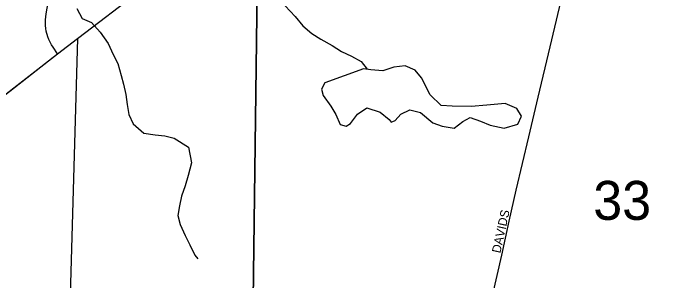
# Model space of a CAD drawing. Extents: x -9.1 to 34, y -3.1 to 22.
# Drawn here: x 3.961 to 4.682, y 18.292 to 18.579 of the extents above; entities that cross this region are included whole.
import ezdxf

# ---------------------------------------------------------------- set-up
doc = ezdxf.new("R2010")
doc.units = 0
for name, color, linetype in [('GM_X_City_Street', 7, 'Continuous'), ('GM_X_City_Street_Text', 7, 'Continuous'), ('GM_X_Corporation', 7, 'Continuous'), ('GM_X_Minor_Lake', 7, 'Continuous'), ('GM_X_Minor_River', 7, 'Continuous'), ('GM_X_Section', 7, 'Continuous'), ('GM_X_Section_Text', 7, 'Continuous'), ('GM_X_State_Route', 7, 'Continuous')]:
    doc.layers.add(name, color=color, linetype=linetype)

msp = doc.modelspace()

# ---------------------------------------------------------------- linework, layer by layer
at = {"layer": 'GM_X_City_Street'}
for points in [[(4.47636, 18.27506), (4.48661, 18.31901), (4.49442, 18.35546), (4.50193, 18.38876), (4.51566, 18.44616), (4.52552, 18.48852), (4.53842, 18.54291), (4.54863, 18.58519), (4.56037, 18.63668), (4.56565, 18.66061)], [(4.00828, 18.5352), (4.00347, 18.54237), (4.00172, 18.54495), (4.00023, 18.5477), (3.99896, 18.55055), (3.99785, 18.55347), (3.99612, 18.55946), (3.99557, 18.56253), (3.99529, 18.56563), (3.99535, 18.57188), (3.996, 18.57809), (3.9981, 18.5904), (3.99988, 18.60277), (4.00132, 18.61517), (4.00215, 18.62763), (4.00231, 18.63659)]]:
    msp.add_lwpolyline(points, dxfattribs=at)
at = {"layer": 'GM_X_Corporation'}
msp.add_lwpolyline([(3.93993, 18.48223), (4.00829, 18.5352), (4.02978, 18.55166), (4.02208, 18.27579), (4.21178, 18.27348), (4.21067, 18.18105), (4.45778, 18.17878), (4.47822, 18.26894), (4.48446, 18.26888), (4.48709, 18.28022), (4.70754, 18.2776)], dxfattribs=at)
at = {"layer": 'GM_X_Minor_Lake'}
for points in [[(4.29607, 18.50411), (4.29255, 18.49735), (4.29433, 18.49049), (4.30246, 18.47898), (4.30799, 18.47016), (4.31273, 18.45946), (4.31912, 18.45746), (4.3237, 18.46041), (4.33105, 18.47052), (4.34137, 18.47717), (4.35566, 18.47275), (4.36536, 18.46462), (4.36758, 18.46193), (4.37177, 18.46375), (4.37793, 18.47047), (4.38746, 18.47524), (4.39913, 18.47238), (4.41218, 18.46116), (4.42233, 18.45757), (4.43515, 18.45545), (4.44472, 18.46249), (4.45235, 18.46691), (4.46363, 18.46293), (4.47414, 18.45857), (4.48921, 18.45528), (4.50365, 18.45958), (4.50757, 18.46823), (4.50279, 18.47666), (4.49002, 18.48181), (4.47034, 18.48025), (4.45368, 18.47864), (4.43327, 18.479), (4.42118, 18.47958), (4.40927, 18.49116), (4.40012, 18.50952), (4.39345, 18.5176), (4.38256, 18.52234), (4.37044, 18.52103), (4.35866, 18.51706), (4.34544, 18.51805), (4.33752, 18.51932)], [(4.33752, 18.51932), (4.29607, 18.50411)]]:
    msp.add_lwpolyline(points, dxfattribs=at)
at = {"layer": 'GM_X_Minor_River'}
for points in [[(4.02896, 18.58417), (4.03483, 18.57308), (4.04497, 18.56911), (4.05425, 18.55871), (4.06275, 18.54643), (4.06822, 18.53459), (4.07336, 18.52502), (4.07693, 18.51207), (4.07942, 18.50254), (4.08188, 18.4915), (4.08322, 18.48086), (4.08494, 18.47022), (4.08968, 18.4599), (4.10124, 18.44984), (4.11331, 18.44812), (4.12388, 18.44718), (4.13404, 18.44472), (4.14938, 18.43498), (4.15251, 18.41824)], [(4.25319, 18.58675), (4.26397, 18.57557), (4.2725, 18.56519), (4.28219, 18.55706), (4.29192, 18.5512), (4.30391, 18.54417), (4.31401, 18.53793), (4.32489, 18.53281), (4.335, 18.52695), (4.34168, 18.51865)], [(4.15251, 18.41824), (4.14889, 18.40466), (4.14568, 18.39334), (4.14172, 18.38241), (4.13965, 18.37183), (4.13797, 18.36162), (4.14046, 18.35172), (4.14556, 18.33988), (4.15069, 18.32993), (4.15618, 18.31884), (4.15952, 18.31499)]]:
    msp.add_lwpolyline(points, dxfattribs=at)
at = {"layer": 'GM_X_Section'}
for points in [[(3.22195, 18.78578), (4.22542, 18.77097), (4.21254, 17.77165), (3.20939, 17.77812)], [(4.22542, 18.77097), (5.22068, 18.771), (5.21493, 17.76405), (4.21254, 17.77165)]]:
    msp.add_lwpolyline(points, close=True, dxfattribs=at)
at = {"layer": 'GM_X_State_Route'}
for points in [[(4.02978, 18.55166), (4.05374, 18.57001), (4.07365, 18.58504), (4.11277, 18.6153), (4.12971, 18.62841), (4.1384, 18.63523), (4.14685, 18.64188), (4.17126, 18.6613), (4.1932, 18.6788), (4.21521, 18.69641), (4.24213, 18.7175), (4.26162, 18.73304), (4.28825, 18.75436), (4.30525, 18.76806), (4.31477, 18.77541)], [(3.71152, 18.30501), (3.76488, 18.3463), (3.78489, 18.36179), (3.81394, 18.38426), (3.81908, 18.38824), (3.85835, 18.41895), (3.88546, 18.43991), (3.90179, 18.45264), (3.91986, 18.46674), (3.93993, 18.48223), (3.95686, 18.49529), (4.00361, 18.53162), (4.00828, 18.5352), (4.02978, 18.55166)]]:
    msp.add_lwpolyline(points, dxfattribs=at)

# ---------------------------------------------------------------- texts
at = {"layer": 'GM_X_City_Street_Text'}
msp.add_text('DAVIDS', height=0.00947, rotation=77.5944, dxfattribs=at).set_placement((4.48494, 18.32045))
at = {"layer": 'GM_X_Section_Text'}
msp.add_text('33', height=0.041856, rotation=0.00001, dxfattribs=at).set_placement((4.58501, 18.35682))

doc.saveas('drawing.dxf')
